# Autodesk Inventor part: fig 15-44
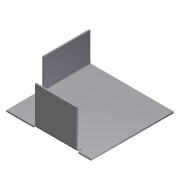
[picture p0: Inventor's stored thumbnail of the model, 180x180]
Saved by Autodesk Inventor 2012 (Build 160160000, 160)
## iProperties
Created: 2005-03
Part Number: fig 15-44
Document SubType Name: Sheet Metal
Designer: CADCIM
Manufacturer: Standard
Standards Organization: Custom
Density: 1 g/cm^3
Sheet Metal Rule: Default
Material: Default
Author: CADCIM
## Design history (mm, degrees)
node "Face1"
  sketch "Sketch1"
    geometry: L1 (-29, -26)-(30, -26); L2 (30, -26)-(30, 31.375); L3 (30, 31.375)-(-29, 31.375); L4 (-29, 31.375)-(-29, -26)
    constraints: 8 end point, 2 parallel, 1 horizontal, 1 perpendicular
node "Flange1"
node "Flange2"
body "Solid1"
face "Plate1" dims "Thickness" = 1
sketch "Sketch2"
  geometry: L1 (25, 0)-(57.375, 0); L2 (57.375, 0)-(57.375, 20); L3 (57.375, 20)-(25, 20); L4 (25, 20)-(25, 0)
  constraints: 8 end point
face "Plate2" dims "d1" = 0, "d2" = 25, "d3" = 1 (= BendReliefWidth), "d5" = 2 (= MinimumRemnant), "d7" = 20, "d8" = 90 deg, "d9" = 1 (= BendRadius), "Thickness" = 1
bend "Bend1" dims "d3" = 1 (= BendReliefWidth), "d4" = 0.5 (= BendReliefDepth), "d5" = 2 (= MinimumRemnant), "d6" = 1 (= BendRadius), "d7" = 20, "d8" = 90 deg, "d9" = 1 (= BendRadius), "SeamGap" = 0.01, "Thickness" = 1
sketch "Sketch3"
  geometry: L1 (10, 0)-(39, 0); L2 (39, 0)-(39, 26); L3 (39, 26)-(10, 26); L4 (10, 26)-(10, 0)
  constraints: 8 end point
face "Plate3" dims "d10" = 20, "d11" = 10, "d12" = 1 (= BendReliefWidth), "d14" = 2 (= MinimumRemnant), "d16" = 26, "d17" = 90 deg, "d18" = 1 (= BendRadius), "Thickness" = 1
bend "Bend2" dims "d12" = 1 (= BendReliefWidth), "d13" = 0.5 (= BendReliefDepth), "d14" = 2 (= MinimumRemnant), "d15" = 1 (= BendRadius), "d16" = 26, "d17" = 90 deg, "d18" = 1 (= BendRadius), "SeamGap" = 0.01, "Thickness" = 1
other parameters: "BendRadius" = 1 (= Thickness), "BendReliefWidth" = 1 (= Thickness), "BendReliefDepth" = 0.5 (= 0.5 x Thickness), "CornerReliefSize" = 4 (= 4 x Thickness), "MinimumRemnant" = 2 (= 2 x Thickness), "TransitionRadius" = 1 (= BendRadius), "d0" = 1 (= BendRadius), "JacobiRadiusSize" = 1 (= Thickness), "GapSize" = 1 (= Thickness)
